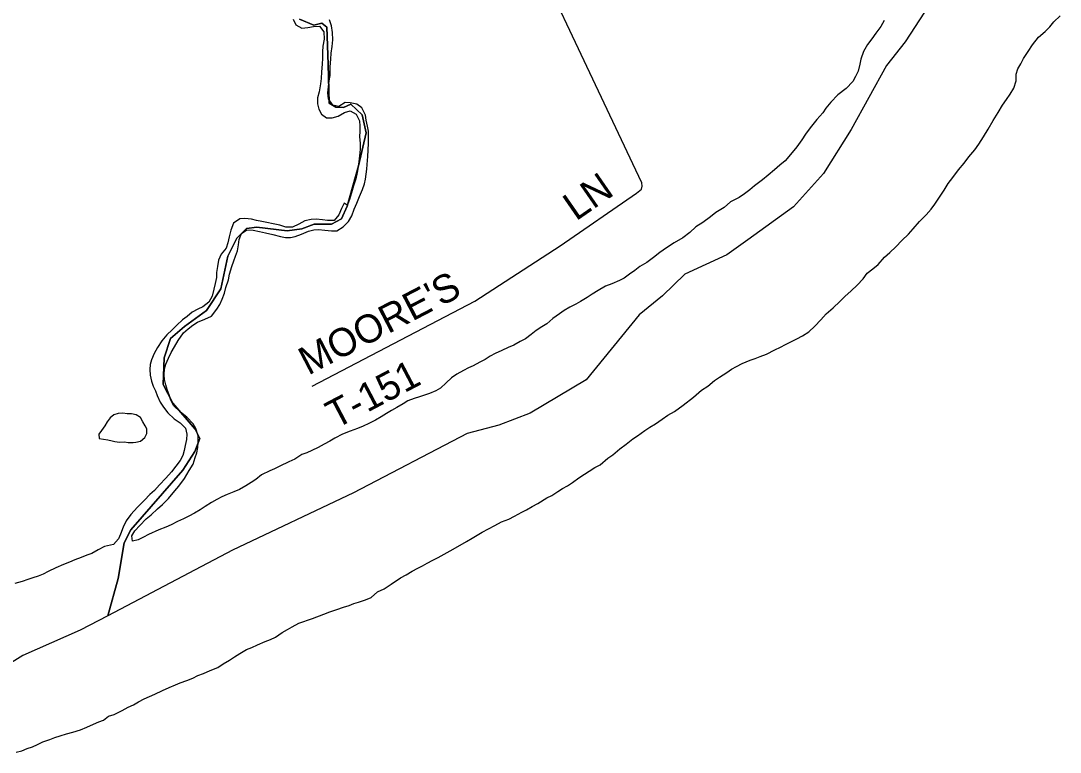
# Model space of a CAD drawing. Extents: x 1624196 to 2029251, y 146837 to 440034.
# Drawn here: x 1802184 to 1813254, y 247823 to 255615 of the extents above; entities that cross this region are included whole.
import ezdxf

# ---------------------------------------------------------------- set-up
doc = ezdxf.new("R2010")
doc.units = 0
for name, color, linetype in [('GM_X_County', 7, 'Continuous'), ('GM_X_Major_River', 7, 'Continuous'), ('GM_X_Minor_Lake', 7, 'Continuous'), ('GM_X_Township', 7, 'Continuous'), ('GM_X_Township_Road', 7, 'Continuous'), ('GM_X_Township_Road_Text', 7, 'Continuous')]:
    doc.layers.add(name, color=color, linetype=linetype)

msp = doc.modelspace()

# ---------------------------------------------------------------- linework, layer by layer
at = {"layer": 'GM_X_County'}
msp.add_lwpolyline([(1812114, 256180), (1811604, 255390), (1811403, 255140), (1811027, 254456), (1810732, 253987), (1810414, 253633), (1809928, 253283), (1809704, 253123), (1809257, 252917), (1809018, 252685), (1808769, 252483), (1808205, 251790), (1807610, 251435), (1807275, 251308), (1806937, 251218), (1805727, 250586), (1804440, 249976), (1803110, 249275), (1802818, 249122), (1802205, 248852), (1801771, 248582)], dxfattribs=at)
at = {"layer": 'GM_X_Major_River'}
for points in [[(1804535, 253349), (1804592, 253387), (1804658, 253383), (1804726, 253372), (1804790, 253356), (1804867, 253337), (1804949, 253316), (1805003, 253308), (1805057, 253308), (1805107, 253317), (1805174, 253341), (1805248, 253373), (1805304, 253388), (1805356, 253390), (1805422, 253386), (1805492, 253377), (1805552, 253379), (1805616, 253419), (1805675, 253476), (1805709, 253536), (1805736, 253608), (1805764, 253672), (1805791, 253742), (1805825, 253818), (1805844, 253877), (1805854, 253929), (1805862, 253981), (1805869, 254035), (1805875, 254085), (1805882, 254171), (1805884, 254237), (1805887, 254310), (1805888, 254440), (1805878, 254492), (1805861, 254555), (1805857, 254611), (1805817, 254687), (1805762, 254726), (1805694, 254742), (1805640, 254743), (1805571, 254701), (1805507, 254715), (1805460, 254782), (1805454, 254846), (1805461, 254910), (1805467, 254976), (1805478, 255033), (1805480, 255125), (1805487, 255207), (1805491, 255271), (1805502, 255343), (1805506, 255414), (1805503, 255490), (1805493, 255562), (1805472, 255627)], [(1805084, 255631), (1805113, 255571), (1805179, 255536), (1805243, 255542), (1805303, 255555), (1805365, 255559), (1805411, 255496), (1805414, 255418), (1805402, 255344), (1805399, 255286), (1805397, 255216), (1805393, 255152), (1805388, 255073), (1805385, 255001), (1805375, 254945), (1805362, 254857), (1805346, 254793), (1805344, 254730), (1805359, 254674), (1805387, 254622), (1805441, 254583), (1805501, 254583), (1805565, 254599), (1805633, 254638), (1805693, 254656), (1805757, 254621), (1805790, 254549), (1805794, 254493), (1805796, 254437), (1805793, 254382), (1805799, 254308), (1805798, 254248), (1805792, 254176), (1805783, 254114), (1805777, 254058), (1805767, 253999), (1805752, 253933), (1805728, 253857), (1805705, 253781), (1805685, 253711), (1805664, 253653), (1805660, 253650)], [(1811381, 255619), (1811344, 255555), (1811292, 255485), (1811247, 255423), (1811201, 255361), (1811160, 255289), (1811132, 255207), (1811120, 255153), (1811103, 255079), (1811073, 255021), (1811044, 254969), (1810974, 254895), (1810885, 254827), (1810812, 254748), (1810758, 254686), (1810726, 254634), (1810661, 254564), (1810592, 254474), (1810542, 254408), (1810504, 254348), (1810451, 254274), (1810382, 254191), (1810326, 254125), (1810269, 254077), (1810213, 254027), (1810143, 253971), (1810082, 253920), (1810000, 253856), (1809949, 253814), (1809891, 253772), (1809835, 253731), (1809742, 253687), (1809674, 253627), (1809586, 253572), (1809531, 253528), (1809449, 253468), (1809372, 253421), (1809308, 253361), (1809235, 253303), (1809143, 253249), (1809061, 253198), (1808990, 253146), (1808922, 253092), (1808851, 253041), (1808779, 252997), (1808723, 252955), (1808668, 252915), (1808610, 252874), (1808560, 252848), (1808480, 252814), (1808411, 252787), (1808333, 252741), (1808271, 252703), (1808216, 252668), (1808146, 252626), (1808094, 252596), (1808030, 252564), (1807973, 252527), (1807921, 252493), (1807849, 252445), (1807786, 252387), (1807734, 252356), (1807672, 252314), (1807621, 252272), (1807559, 252226), (1807503, 252197), (1807434, 252161), (1807376, 252135), (1807308, 252104), (1807236, 252072), (1807182, 252042), (1807129, 252008), (1807073, 251979), (1807003, 251941), (1806952, 251917), (1806900, 251891), (1806828, 251850), (1806770, 251810), (1806715, 251758), (1806655, 251702), (1806603, 251673), (1806538, 251645), (1806484, 251625), (1806430, 251608), (1806374, 251592), (1806306, 251566), (1806255, 251536)], [(1809350, 251605), (1809434, 251679), (1809500, 251724), (1809573, 251782), (1809627, 251820), (1809704, 251869), (1809754, 251903), (1809808, 251931), (1809868, 251963), (1809951, 252000), (1810007, 252018), (1810059, 252040), (1810125, 252063), (1810214, 252109), (1810274, 252137), (1810328, 252166), (1810380, 252190), (1810449, 252226), (1810509, 252258), (1810577, 252301), (1810642, 252361), (1810706, 252429), (1810763, 252495), (1810837, 252558), (1810906, 252626), (1810962, 252678), (1811028, 252740), (1811093, 252800), (1811155, 252867), (1811198, 252925), (1811260, 252973), (1811315, 253019), (1811383, 253097), (1811440, 253146), (1811504, 253208), (1811569, 253274), (1811639, 253342), (1811689, 253400), (1811754, 253478), (1811825, 253549), (1811879, 253607), (1811919, 253663), (1811968, 253735), (1812019, 253809), (1812061, 253883), (1812112, 253947), (1812172, 254029), (1812231, 254100), (1812281, 254166), (1812346, 254240), (1812386, 254302), (1812437, 254378), (1812487, 254460), (1812540, 254552), (1812595, 254638), (1812639, 254716), (1812682, 254776), (1812720, 254834), (1812759, 254896), (1812785, 254974), (1812784, 255048), (1812802, 255102), (1812834, 255156), (1812863, 255212), (1812913, 255288), (1812960, 255358), (1813023, 255442), (1813093, 255502), (1813145, 255551), (1813186, 255603), (1813254, 255669)], [(1805660, 253650), (1805628, 253671), (1805600, 253615), (1805571, 253547), (1805523, 253487), (1805451, 253488), (1805397, 253496), (1805329, 253501), (1805277, 253499), (1805211, 253485), (1805146, 253450), (1805078, 253416), (1805006, 253416), (1804942, 253439), (1804872, 253453), (1804806, 253466), (1804752, 253478), (1804694, 253487), (1804640, 253501), (1804569, 253510), (1804516, 253504), (1804450, 253460), (1804420, 253384), (1804403, 253314), (1804389, 253250), (1804372, 253192), (1804320, 253128), (1804291, 253064), (1804281, 252998), (1804268, 252934), (1804268, 252881), (1804255, 252817), (1804241, 252757), (1804222, 252683), (1804188, 252619), (1804122, 252569), (1804069, 252544), (1804011, 252510), (1803957, 252464), (1803905, 252430), (1803848, 252373), (1803798, 252323), (1803741, 252271), (1803687, 252205), (1803640, 252135), (1803604, 252069), (1803575, 252003), (1803561, 251953), (1803559, 251901), (1803564, 251839), (1803578, 251776), (1803595, 251724), (1803619, 251674), (1803637, 251623), (1803670, 251553), (1803704, 251499), (1803749, 251440), (1803819, 251374), (1803883, 251333), (1803940, 251276), (1803952, 251210), (1803950, 251156), (1803935, 251092), (1803923, 251036), (1803910, 250984), (1803880, 250932), (1803837, 250872), (1803791, 250810), (1803728, 250744), (1803660, 250670), (1803609, 250612), (1803559, 250567), (1803503, 250509), (1803428, 250433), (1803356, 250355), (1803305, 250287), (1803273, 250219), (1803246, 250147), (1803226, 250097), (1803171, 250037), (1803077, 250014), (1803009, 249980), (1802942, 249940), (1802888, 249923), (1802828, 249897), (1802760, 249871), (1802702, 249848), (1802641, 249824), (1802559, 249788), (1802477, 249747), (1802423, 249719), (1802368, 249699), (1802314, 249682), (1802258, 249662), (1802198, 249642), (1802122, 249619)], [(1806255, 251536), (1806191, 251497), (1806131, 251463), (1806081, 251431), (1806024, 251397), (1805962, 251362), (1805890, 251326), (1805830, 251298), (1805769, 251273), (1805691, 251243), (1805609, 251210), (1805528, 251168), (1805476, 251138), (1805416, 251106), (1805350, 251069), (1805283, 251037), (1805231, 251011), (1805179, 250994), (1805103, 250946), (1805038, 250918), (1804944, 250869), (1804888, 250843), (1804838, 250819), (1804749, 250778), (1804687, 250728), (1804637, 250696), (1804580, 250660), (1804514, 250623), (1804454, 250597), (1804384, 250569), (1804325, 250544), (1804271, 250516), (1804217, 250484), (1804149, 250440), (1804096, 250405), (1804034, 250369), (1803974, 250339), (1803916, 250309), (1803853, 250280), (1803787, 250244), (1803729, 250220), (1803655, 250191), (1803546, 250143), (1803490, 250114), (1803436, 250086), (1803374, 250072), (1803366, 250128), (1803398, 250180), (1803453, 250240), (1803519, 250308), (1803572, 250352), (1803640, 250416), (1803694, 250461), (1803759, 250527), (1803824, 250607), (1803866, 250659), (1803929, 250739), (1803977, 250823), (1804020, 250893), (1804042, 250963), (1804061, 251013), (1804069, 251069), (1804073, 251129), (1804074, 251195), (1804050, 251270), (1804019, 251322), (1803951, 251391), (1803882, 251449), (1803816, 251514), (1803784, 251574), (1803765, 251629), (1803745, 251687), (1803730, 251737), (1803714, 251792), (1803710, 251842), (1803715, 251906), (1803729, 251956), (1803756, 252022), (1803786, 252080), (1803822, 252140), (1803861, 252210), (1803916, 252290), (1803966, 252334), (1804016, 252371), (1804068, 252403), (1804145, 252435), (1804215, 252470), (1804274, 252542), (1804304, 252594), (1804330, 252648), (1804353, 252714), (1804369, 252774), (1804396, 252855), (1804408, 252915), (1804433, 252997), (1804455, 253057), (1804472, 253107), (1804492, 253163), (1804502, 253227), (1804511, 253285), (1804535, 253349)], [(1802739, 248038), (1802819, 248063), (1802887, 248089), (1802957, 248121), (1803014, 248146), (1803064, 248166), (1803120, 248206), (1803180, 248226), (1803265, 248269), (1803329, 248303), (1803383, 248327), (1803439, 248360), (1803500, 248390), (1803554, 248416), (1803612, 248443), (1803692, 248481), (1803763, 248513), (1803831, 248542), (1803883, 248562), (1803953, 248586), (1804018, 248611), (1804070, 248641), (1804132, 248663), (1804202, 248692), (1804282, 248724), (1804341, 248764), (1804407, 248805), (1804461, 248839), (1804518, 248873), (1804588, 248917), (1804644, 248940), (1804704, 248968), (1804787, 249002), (1804845, 249023), (1804897, 249049), (1804969, 249097), (1805024, 249131), (1805074, 249158), (1805146, 249196), (1805291, 249247), (1805411, 249295), (1805477, 249320), (1805550, 249344), (1805620, 249368), (1805680, 249387), (1805730, 249407), (1805780, 249423), (1805856, 249446), (1805915, 249472), (1805985, 249530), (1806055, 249565), (1806130, 249615), (1806228, 249681), (1806289, 249714), (1806351, 249750), (1806413, 249784), (1806463, 249810), (1806514, 249837), (1806574, 249869), (1806628, 249899), (1806692, 249932), (1806759, 249970), (1806813, 250002), (1806933, 250069), (1806992, 250105), (1807044, 250135), (1807098, 250167), (1807164, 250202), (1807233, 250240), (1807305, 250278), (1807383, 250307), (1807444, 250337), (1807522, 250379), (1807572, 250404), (1807630, 250442), (1807691, 250472), (1807787, 250533), (1807841, 250559), (1807904, 250599), (1807954, 250633), (1808006, 250660), (1808060, 250696), (1808127, 250746), (1808187, 250786), (1808237, 250817), (1808298, 250857), (1808356, 250885), (1808438, 250957), (1808489, 250990), (1808563, 251054), (1808632, 251106), (1808702, 251160), (1808754, 251195), (1808829, 251249), (1808885, 251287), (1808943, 251320), (1809016, 251370), (1809076, 251412), (1809148, 251452), (1809239, 251521), (1809350, 251605)], [(1802135, 247823), (1802197, 247839), (1802253, 247864), (1802309, 247880), (1802364, 247906), (1802420, 247933), (1802492, 247959), (1802546, 247979), (1802602, 247996), (1802671, 248020), (1802739, 248038)]]:
    msp.add_lwpolyline(points, dxfattribs=at)
at = {"layer": 'GM_X_Minor_Lake'}
for points in [[(1803334, 251428), (1803319, 251428), (1803271, 251435), (1803223, 251433), (1803177, 251417), (1803135, 251385), (1803104, 251343), (1803078, 251299), (1803044, 251252), (1803017, 251210), (1803019, 251165), (1803065, 251159), (1803111, 251151), (1803159, 251140), (1803187, 251134)], [(1803187, 251134), (1803235, 251126), (1803289, 251128), (1803329, 251123), (1803381, 251123), (1803411, 251125), (1803459, 251136), (1803507, 251174), (1803526, 251220), (1803526, 251267), (1803510, 251299), (1803483, 251343), (1803459, 251389), (1803413, 251416), (1803365, 251428), (1803334, 251428)]]:
    msp.add_lwpolyline(points, dxfattribs=at)
at = {"layer": 'GM_X_Township'}
for points in [[(1812114, 256180), (1811604, 255390), (1811403, 255140), (1811027, 254456), (1810732, 253987), (1810414, 253633), (1809928, 253283), (1809704, 253123), (1809257, 252917), (1809018, 252685), (1808769, 252483), (1808205, 251790), (1807610, 251435), (1807275, 251308), (1806937, 251218), (1805727, 250586), (1804440, 249976), (1803110, 249275), (1803220, 249674), (1803285, 250052), (1803358, 250192), (1803911, 250826), (1804037, 251026), (1804092, 251165), (1804041, 251266), (1803805, 251541), (1803701, 251739), (1803711, 252026), (1803779, 252231), (1803929, 252357), (1804161, 252530), (1804316, 252760), (1804388, 253107), (1804484, 253298), (1804589, 253404), (1804700, 253418), (1805023, 253378), (1805178, 253398), (1805308, 253449), (1805492, 253447), (1805599, 253505), (1805660, 253640), (1805780, 254071), (1805864, 254420), (1805819, 254615), (1805699, 254727), (1805622, 254692), (1805538, 254695), (1805469, 254737), (1805457, 255152), (1805445, 255547), (1805390, 255590), (1805305, 255570), (1805151, 255632)], [(1805151, 255632), (1805305, 255570), (1805390, 255590), (1805445, 255547), (1805457, 255152), (1805469, 254737), (1805538, 254695), (1805622, 254692), (1805699, 254727), (1805819, 254615), (1805864, 254420), (1805780, 254071), (1805660, 253640), (1805599, 253505), (1805492, 253447), (1805308, 253449), (1805178, 253398), (1805023, 253378), (1804700, 253418), (1804589, 253404), (1804484, 253298), (1804388, 253107), (1804316, 252760), (1804161, 252530), (1803929, 252357), (1803779, 252231), (1803711, 252026), (1803701, 251739), (1803805, 251541), (1804041, 251266), (1804092, 251165), (1804037, 251026), (1803911, 250826), (1803358, 250192), (1803285, 250052), (1803220, 249674), (1803110, 249275), (1802818, 249122), (1802205, 248852), (1801771, 248582)]]:
    msp.add_lwpolyline(points, dxfattribs=at)
at = {"layer": 'GM_X_Township_Road'}
msp.add_lwpolyline([(1805287, 251721), (1807020, 252629), (1807929, 253218), (1808743, 253777), (1808796, 253820), (1808803, 253855), (1808799, 253888), (1808736, 254023), (1807205, 257265)], dxfattribs=at)

# ---------------------------------------------------------------- texts
at = {"layer": 'GM_X_Township_Road_Text'}
for s, rotation, p in [('LN', 34.6951, (1808097, 253476)), ("MOORE'S", 27.4857, (1805246, 251834)), ('T-151', 27.6936, (1805538, 251263))]:
    msp.add_text(s, height=300, rotation=rotation, dxfattribs=at).set_placement(p)

doc.saveas('drawing.dxf')
